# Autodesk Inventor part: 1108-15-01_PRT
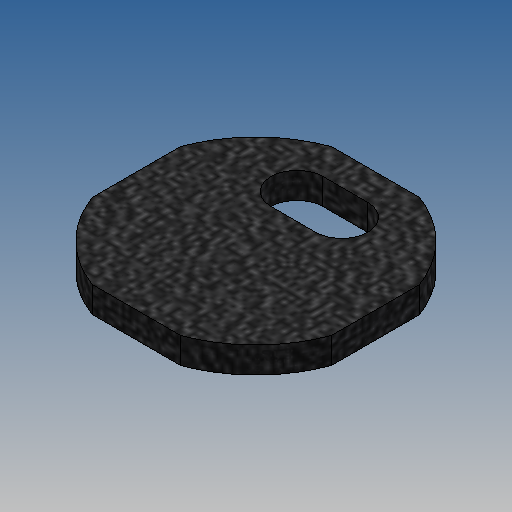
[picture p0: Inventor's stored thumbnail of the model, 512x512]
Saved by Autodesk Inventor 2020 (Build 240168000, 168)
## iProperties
Created: 2007-03
Part Number: 1108-15-01_PRT
Document SubType Name: Modeling
Designer: Andy Moles
Material: ABS Plastic
Mass: 1.09503 g
Surface Area: 10.7786 cm^2
Volume: 1.03305 cm^3
Density: 1.06 g/cm^3
Appearance: Black Cast
Author: Andy Moles
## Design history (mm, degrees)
workplane "Work Plane1"
sketch "Sketch1"
  geometry: L1 (-2.019, 0.4)-(6.481, 0.4) reference; L2 (-2.019, -4.646)-(-2.019, 0.4) reference; L3 (-2.019, -12.589)-(-2.019, -6.554) reference; L4 (-9.269, 3.12)-(-9.269, -5.32) reference; L5 (6.452, 10.4)-(-1.989, 10.4) reference; L6 (13.731, -5.32)-(13.731, 3.12) reference; L7 (6.481, -12.589)-(6.481, -6.554) reference; L8 (6.481, 0.4)-(6.481, -4.646) reference; L9 (0.081, 2.5)-(4.381, 2.5) reference; L10 (4.381, 7.5)-(0.081, 7.5) reference; L11 (7.481, -9.75)-(7.481, 0.05) reference; L12 (9.181, 1.45)-(9.181, -9.75) reference; L13 (-3.869, 2.3)-(8.331, 2.3) reference; L14 (-4.719, -9.75)-(-4.719, 1.45) reference; L15 (-3.019, 0.05)-(-3.019, -9.75) reference; L16 (6.931, 0.6)-(-2.469, 0.6) reference; L17 (-6.569, 2.497)-(-6.569, -4.697) reference; L18 (5.828, 7.7)-(-1.366, 7.7) reference; L19 (11.031, -4.697)-(11.031, 2.497) reference; L20 (12.731, 2.778)-(12.731, -4.978) reference; L21 (-1.646, 9.4)-(6.109, 9.4) reference; L22 (-8.269, -4.978)-(-8.269, 2.778) reference; L23 (6.481, -12.589)-(-2.019, -12.589); A1 r 1 centre (-1.719, -5.6) between (-2.019, -6.554) and (-2.019, -4.646) reference; A2 r 12.25 centre (2.231, -1.1) between (-9.269, -5.32) and (-2.019, -12.589) reference; A3 r 12.25 centre (2.231, -1.1) between (-1.989, 10.4) and (-9.269, 3.12) reference; A4 r 12.25 centre (2.231, -1.1) between (13.731, 3.12) and (6.452, 10.4) reference; A5 r 12.25 centre (2.231, -1.1) between (6.481, -12.589) and (13.731, -5.32) reference; A6 r 1 centre (6.181, -5.6) between (6.481, -4.646) and (6.481, -6.554) reference; A7 r 2.5 centre (0.081, 5) between (0.081, 7.5) and (0.081, 2.5) reference; A8 r 2.5 centre (4.381, 5) between (4.381, 2.5) and (4.381, 7.5) reference; A9 r 0.55 centre (6.931, 0.05) between (7.481, 0.05) and (6.931, 0.6) reference; A10 r 0.85 centre (8.331, -9.75) between (7.481, -9.75) and (9.181, -9.75) reference; A11 r 0.85 centre (8.331, 1.45) between (9.181, 1.45) and (8.331, 2.3) reference; A12 r 0.85 centre (-3.869, 1.45) between (-3.869, 2.3) and (-4.719, 1.45) reference; A13 r 0.85 centre (-3.869, -9.75) between (-4.719, -9.75) and (-3.019, -9.75) reference; A14 r 0.55 centre (-2.469, 0.05) between (-2.469, 0.6) and (-3.019, 0.05) reference; A15 r 0.55 centre (-6.019, -4.697) between (-6.569, -4.697) and (-6.523, -4.917) reference; A16 r 0.55 centre (-6.019, 2.497) between (-6.523, 2.717) and (-6.569, 2.497) reference; A17 r 9.55 centre (2.231, -1.1) between (-1.585, 7.654) and (-6.523, 2.717) reference; A18 r 0.55 centre (-1.366, 7.15) between (-1.366, 7.7) and (-1.585, 7.654) reference; A19 r 0.55 centre (5.828, 7.15) between (6.048, 7.654) and (5.828, 7.7) reference; A20 r 9.55 centre (2.231, -1.1) between (10.986, 2.717) and (6.048, 7.654) reference; A21 r 0.55 centre (10.481, 2.497) between (11.031, 2.497) and (10.986, 2.717) reference; A22 r 0.55 centre (10.481, -4.697) between (10.986, -4.917) and (11.031, -4.697) reference; A23 r 9.55 centre (2.231, -1.1) between (9.933, -6.747) and (10.986, -4.917) reference; A24 r 0.85 centre (10.618, -7.25) between (9.933, -6.747) and (11.304, -7.753) reference; A25 r 11.25 centre (2.231, -1.1) between (11.304, -7.753) and (12.67, -5.295) reference; A26 r 0.85 centre (11.881, -4.978) between (12.67, -5.295) and (12.731, -4.978) reference; A27 r 0.85 centre (11.881, 2.778) between (12.731, 2.778) and (12.67, 3.095) reference; A28 r 11.25 centre (2.231, -1.1) between (12.67, 3.095) and (6.426, 9.339) reference; A29 r 0.85 centre (6.109, 8.55) between (6.426, 9.339) and (6.109, 9.4) reference; A30 r 0.85 centre (-1.646, 8.55) between (-1.646, 9.4) and (-1.963, 9.339) reference; A31 r 11.25 centre (2.231, -1.1) between (-1.963, 9.339) and (-8.207, 3.095) reference; A32 r 0.85 centre (-7.419, 2.778) between (-8.207, 3.095) and (-8.269, 2.778) reference; A33 r 0.85 centre (-7.419, -4.978) between (-8.269, -4.978) and (-8.207, -5.295) reference; A34 r 11.25 centre (2.231, -1.1) between (-8.207, -5.295) and (-6.761, -7.86) reference; A35 r 0.85 centre (-6.082, -7.349) between (-6.761, -7.86) and (-5.402, -6.838) reference; A36 r 9.55 centre (2.231, -1.1) between (-6.523, -4.917) and (-5.402, -6.838) reference; 2 further points
  constraints: 2 end point, 1 perpendicular
extrude "Extrusion1" new body sketch "Sketch1" distance "d0" = 2.5; taper "d1" = 0 deg
body "Solid1"
node "Projected Loop1"
